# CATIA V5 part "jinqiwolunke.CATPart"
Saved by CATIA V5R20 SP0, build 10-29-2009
Part number: jinqiwolunke
Material "无"
Bounding box of the stored display mesh (mm): x -94.684 to 94.684, y -113 to 94.497, z 0 to 114.557
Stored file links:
  C:\Users\Administrator\Desktop\jinqiwolunke.CATPart
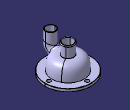
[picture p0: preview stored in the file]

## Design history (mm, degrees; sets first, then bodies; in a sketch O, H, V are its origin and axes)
Body1 (main body), material "无"
  Sketch1 on xy-plane, origin (0, 0, 0), H (1, 0, 0), V (0, 1, 0)
    circle A1 centre (0, 0) radius 94.6842
    circle A2 centre (0, 0) radius 51.7471
  Pad1: profile Sketch1, direction (0, 0, 1), length 12
  DatumCurve1
  DatumCurve2
  Sketch2 on start face of Pad1, origin (0, 0, 0), H (1, 0, 0), V (0, 1, 0)
    projected circle E1 centre (0, 0) radius 69 from edge of DatumCurve2
  Pocket1: profile Sketch2, direction (0, 0, 1), length 8
  Fillet1: radius 1.5, on edge [face of Pocket1 from Sketch2.E1 | start face of Pad1]; edge [start face of Pad1 | face of Pad1 from Sketch1.A1]
  DatumSurface1
  DatumCurve3
  Sketch3 on face of DatumSurface1, origin (0, 0, 5.9732), H (1, 0, 0), V (0, 1, 0)
    projected circle E1 centre (0, 0) radius 52 from edge of DatumCurve3
  Pocket2: profile Sketch3, direction (0, 0, 1), length 8
  Sketch4 on start face of Pad1, origin (0, 0, 0), H (1, 0, 0), V (0, 1, 0)
    circle A1 centre (0, 78.8118) radius 7.9799
    point P1 (0, 78.8118)
    circle A2 centre (-78.8118, 0) radius 7.9799
    circle A3 centre (0, -78.8118) radius 7.9799
    circle A4 centre (78.8118, 0) radius 7.9799
    coincidence: P1 V
  Pocket3: profile Sketch4, direction (0, 0, 1), length 12, mirrored extent
  Fillet2: radius 0.5, on edge [face of Pocket3 from Sketch4.A1 | start face of Pad1]; edge [face of Pocket3 from Sketch4.A2 | start face of Pad1]; edge [face of Pocket3 from Sketch4.A4 | start face of Pad1]; edge [face of Pocket3 from Sketch4.A3 | start face of Pad1]
  Sketch5 on zx-plane, origin (0, 0, 0), H (-1, 0, 0), V (0, 0, 1)
    spline S1 through (-66.0951, 12) (-66.0951, 25.1645) (-60.5374, 51.4379) (-22.5835, 67.6061)
    line L1 (-22.5835, 67.6061) -> (-22.5835, 109.0174)
    point P1 (-22.5835, 67.6061)
    spline S2 through (-62.5298, 12) (-62.5298, 25.1645) (-55.1524, 53.0115) (-20.2558, 64.3882)
    line L2 (-20.2558, 64.3882) -> (-20.2558, 113.3635)
    point P3 (-20.2558, 64.3882)
    line L3 (-22.5877, 113.8774) -> (-24.8391, 109.0174)
    line L4 (-24.8391, 109.0174) -> (-22.5835, 109.0174)
    line L5 (-66.0951, 12) -> (-62.5298, 12)
    point P4 (-66.0951, 12)
    point P5 (-62.5298, 12)
    reference projected line E1 (-94.6842, 12) -> (94.6842, 12) from edge [face of Pad1 from Sketch1.A1 | end face of Pad1]
    arc A1 centre (-21.4784, 113.3635) radius 1.2226 from (-22.5877, 113.8774) to (-20.2558, 113.3635) cw
    point P10 (-22.5835, 67.6061)
    point P11 (-20.2558, 64.3882)
    point P12 (-66.0951, 12)
    point P13 (-62.5298, 12)
    radius A1 = 1.2226
    coincidence: P10 P1, P11 P3, P12 P4, P13 P5, L5 E1
    vertical: L1 V, L2 V
    horizontal: L4 H, L5 H
    tangency: A1 L3, A1 L2
  Shaft1: profile Sketch5, axis Z axis, angle 360
  Fillet3: radius 0.5, on edge [face of Shaft1 from Sketch5.L4 | face of Shaft1 from Sketch5.L3]; edge [face of Shaft1 from Sketch5.L1 | face of Shaft1 from Sketch5.L4]
  Fillet4: radius 0.5, on edge [face of Shaft1 from Sketch5.S1 | face of Shaft1 from Sketch5.L1]
  Plane1: type Offset, RefPlane zx-plane, Offset -75
  Sketch6 on Plane1, origin (0, -75, 0), H (-1, 0, 0), V (0, 0, 1)
    circle A1 centre (20.59, 33.6508) radius 18.9102
  Pocket4: profile Sketch6, direction (0, 1, 0), length 45
  Sketch7 on Plane1, origin (0, -75, 0), H (-1, 0, 0), V (0, 0, 1)
    line L1 (22.0959, 0) -> (22.0959, 64.6879)
    point P1 (22.0959, 0)
    coincidence: P1 H
    vertical: L1 V
  Plane2: type Angle, RefPlane Plane1, Direction Sketch7, Angle 90
  Sketch8 on Plane2, origin (-22.0959, 0, 0), H (0, -1, 0), V (0, 0, 1)
    point P1 (49.974, 31.6171)
    line L1 (49.974, 31.6171) -> (69.3952, 31.6171)
    line L2 (94.113, 56.3349) -> (94.113, 114.6767)
    point P2 (94.113, 114.6767)
    arc A1 centre (69.3952, 56.3349) radius 24.7177 from (69.3952, 31.6171) to (94.113, 56.3349) ccw
    radius A1 = 24.7177
    horizontal: L1 H
    vertical: L2 V
    tangency: A1 L1, A1 L2
  Plane3: type OffsetPt, RefPlane zx-plane, RefPoint Sketch8.P1
  Sweep1: type Unspec, Profile edge [face of Pocket4 from Sketch6.A1 | face of Shaft1 from Sketch5.S1], Guide Sketch8
  ThickSurface1: Surface Sweep1, TopOffset 2, BotOffset 1
  Plane4: type OffsetPt, RefPlane xy-plane, RefPoint Sketch8.P2
  Plane5: type Offset, RefPlane Plane4, Offset -12
  Sketch9 on Plane5, origin (0, 0, 102.6767), H (1, 0, 0), V (0, 1, 0)
    circle A1 centre (-20.4084, -91.8373) radius 24.3279
  Pocket5: profile Sketch9, direction (0, 0, 1), length 20
  Sketch10 on Plane2, origin (-22.0959, 0, 0), H (0, -1, 0), V (0, 0, 1)
    line L1 (92.0793, 137.7134) -> (92.0793, 78.8715)
    vertical: L1 V
  Fillet5: radius 1, on edge [start face of Pocket5 | face of ThickSurface1]
  Fillet6: radius 1, on edge [face of Pad1 from Sketch1.A1 | end face of Pad1]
